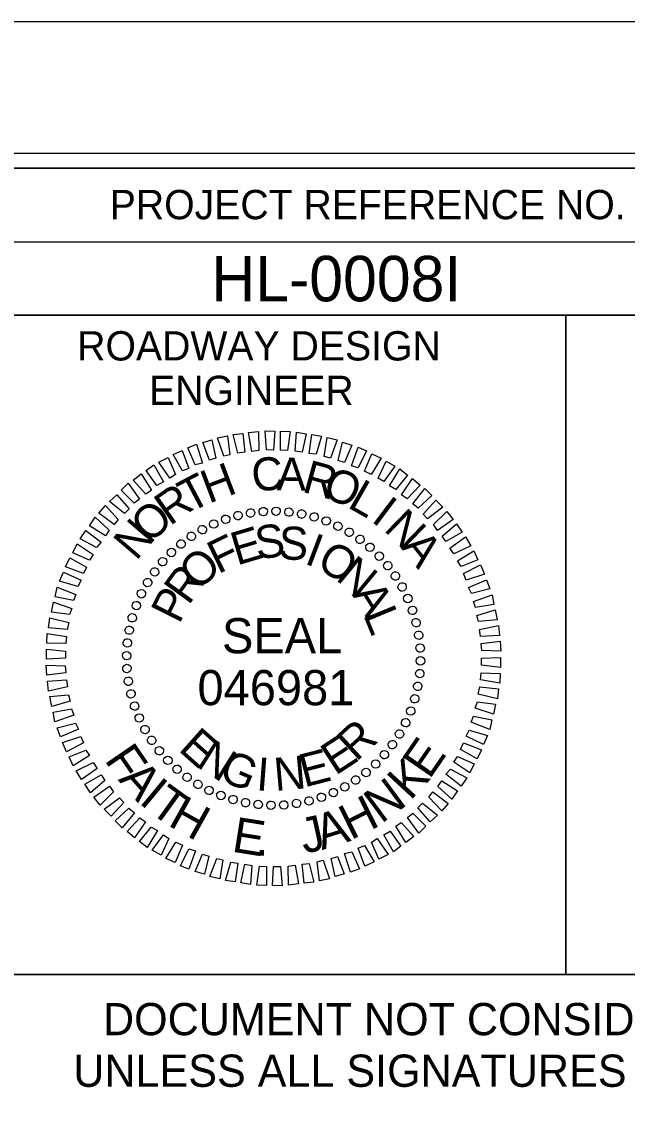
# Model space of a CAD drawing. Extents: x 1629737 to 1631945, y 1172886 to 1173986.
# Drawn here: x 1631211.5 to 1631314.8, y 1173800.4 to 1173985.9 of the extents above; entities that cross this region are included whole.
import ezdxf

# ---------------------------------------------------------------- set-up
doc = ezdxf.new("R2010")
doc.units = 0
for name, color, linetype in [('Sheet Data Field CELL', 7, 'Continuous'), ('Sheet PE Seal Cell', 7, 'Continuous'), ('Sheet Plot Border Inside CELL', 7, 'Continuous'), ('Sheet Plot Border Outside CELL', 7, 'Continuous'), ('Sheet Profile CELL', 7, 'Continuous'), ('Sheet Sticker Exception Certification CELL', 7, 'Continuous')]:
    doc.layers.add(name, color=color, linetype=linetype)

msp = doc.modelspace()

# ---------------------------------------------------------------- linework, layer by layer
at = {"layer": 'Sheet PE Seal Cell'}
for p, q in [((1631250.53, 1173902.1), (1631250.53, 1173902.1)), ((1631252.68, 1173902.4), (1631252.68, 1173902.4)), ((1631254.88, 1173902.45), (1631254.88, 1173902.45)), ((1631257.08, 1173902.3), (1631257.08, 1173902.3)), ((1631244.23, 1173900.3), (1631244.23, 1173900.3)), ((1631246.23, 1173901.1), (1631246.23, 1173901.1)), ((1631248.33, 1173901.7), (1631248.33, 1173901.7)), ((1631259.23, 1173901.95), (1631259.23, 1173901.95)), ((1631261.33, 1173901.5), (1631261.33, 1173901.5)), ((1631263.43, 1173900.8), (1631263.43, 1173900.8)), ((1631242.28, 1173899.3), (1631242.28, 1173899.3)), ((1631265.43, 1173899.9), (1631265.43, 1173899.9)), ((1631267.38, 1173898.9), (1631267.38, 1173898.9)), ((1631238.63, 1173896.9), (1631238.63, 1173896.9)), ((1631240.38, 1173898.15), (1631240.38, 1173898.15)), ((1631269.18, 1173897.65), (1631269.18, 1173897.65)), ((1631236.98, 1173895.4), (1631236.98, 1173895.4)), ((1631270.93, 1173896.3), (1631270.93, 1173896.3)), ((1631272.48, 1173894.8), (1631272.48, 1173894.8)), ((1631235.48, 1173893.85), (1631235.48, 1173893.85)), ((1631273.98, 1173893.15), (1631273.98, 1173893.15)), ((1631234.13, 1173892.1), (1631234.13, 1173892.1)), ((1631275.23, 1173891.4), (1631275.23, 1173891.4)), ((1631232.88, 1173890.3), (1631232.88, 1173890.3)), ((1631276.38, 1173889.5), (1631276.38, 1173889.5)), ((1631231.88, 1173888.35), (1631231.88, 1173888.35)), ((1631277.38, 1173887.55), (1631277.38, 1173887.55)), ((1631230.98, 1173886.35), (1631230.98, 1173886.35)), ((1631278.18, 1173885.55), (1631278.18, 1173885.55)), ((1631230.28, 1173884.25), (1631230.28, 1173884.25)), ((1631229.83, 1173882.15), (1631229.83, 1173882.15)), ((1631278.78, 1173883.45), (1631278.78, 1173883.45)), ((1631229.48, 1173880), (1631229.48, 1173880)), ((1631279.18, 1173881.25), (1631279.18, 1173881.25)), ((1631279.48, 1173879.1), (1631279.48, 1173879.1)), ((1631229.33, 1173877.8), (1631229.33, 1173877.8)), ((1631254.43, 1173877.35), (1631254.43, 1173877.35)), ((1631279.53, 1173876.9), (1631279.53, 1173876.9)), ((1631229.38, 1173875.6), (1631229.38, 1173875.6)), ((1631279.38, 1173874.7), (1631279.38, 1173874.7)), ((1631229.68, 1173873.45), (1631229.68, 1173873.45)), ((1631279.03, 1173872.55), (1631279.03, 1173872.55)), ((1631230.08, 1173871.25), (1631230.08, 1173871.25)), ((1631230.68, 1173869.15), (1631230.68, 1173869.15)), ((1631278.58, 1173870.45), (1631278.58, 1173870.45)), ((1631231.48, 1173867.15), (1631231.48, 1173867.15)), ((1631277.88, 1173868.35), (1631277.88, 1173868.35)), ((1631232.48, 1173865.2), (1631232.48, 1173865.2)), ((1631276.98, 1173866.35), (1631276.98, 1173866.35)), ((1631233.63, 1173863.3), (1631233.63, 1173863.3)), ((1631275.98, 1173864.4), (1631275.98, 1173864.4)), ((1631234.88, 1173861.55), (1631234.88, 1173861.55)), ((1631274.73, 1173862.6), (1631274.73, 1173862.6)), ((1631236.38, 1173859.9), (1631236.38, 1173859.9)), ((1631273.38, 1173860.85), (1631273.38, 1173860.85)), ((1631237.93, 1173858.4), (1631237.93, 1173858.4)), ((1631270.23, 1173857.8), (1631270.23, 1173857.8)), ((1631271.88, 1173859.3), (1631271.88, 1173859.3)), ((1631239.68, 1173857.05), (1631239.68, 1173857.05)), ((1631241.48, 1173855.8), (1631241.48, 1173855.8)), ((1631268.48, 1173856.55), (1631268.48, 1173856.55)), ((1631243.43, 1173854.8), (1631243.43, 1173854.8)), ((1631245.43, 1173853.9), (1631245.43, 1173853.9)), ((1631264.63, 1173854.4), (1631264.63, 1173854.4)), ((1631266.58, 1173855.4), (1631266.58, 1173855.4)), ((1631247.53, 1173853.2), (1631247.53, 1173853.2)), ((1631249.63, 1173852.75), (1631249.63, 1173852.75)), ((1631251.78, 1173852.4), (1631251.78, 1173852.4)), ((1631253.98, 1173852.25), (1631253.98, 1173852.25)), ((1631256.18, 1173852.3), (1631256.18, 1173852.3)), ((1631258.33, 1173852.6), (1631258.33, 1173852.6)), ((1631260.53, 1173853), (1631260.53, 1173853)), ((1631262.63, 1173853.6), (1631262.63, 1173853.6))]:
    msp.add_line(p, q, dxfattribs=at)
for points in [[(1631245.93, 1173911.8), (1631244.88, 1173914.95), (1631246.58, 1173915.3), (1631246.98, 1173912.05)], [(1631248.33, 1173912.35), (1631247.53, 1173915.55), (1631249.18, 1173915.7), (1631249.53, 1173912.5)], [(1631250.73, 1173912.65), (1631250.18, 1173915.85), (1631251.88, 1173916.05), (1631251.93, 1173912.8)], [(1631253.23, 1173912.9), (1631252.98, 1173916.15), (1631254.63, 1173916.1), (1631254.43, 1173912.85)], [(1631255.63, 1173912.85), (1631255.63, 1173916.1), (1631257.28, 1173916.05), (1631256.83, 1173912.8)], [(1631258.13, 1173912.7), (1631258.33, 1173915.95), (1631259.98, 1173915.65), (1631259.33, 1173912.5)], [(1631260.53, 1173912.3), (1631260.98, 1173915.5), (1631262.63, 1173915.25), (1631261.73, 1173912.15)], [(1631241.08, 1173910.35), (1631239.78, 1173913.25), (1631241.28, 1173913.85), (1631242.33, 1173910.65)], [(1631243.53, 1173911.15), (1631242.38, 1173914.15), (1631243.93, 1173914.6), (1631244.58, 1173911.5)], [(1631263.08, 1173911.75), (1631263.58, 1173915), (1631265.28, 1173914.6), (1631264.13, 1173911.5)], [(1631265.48, 1173911.1), (1631266.23, 1173914.2), (1631267.78, 1173913.7), (1631266.53, 1173910.75)], [(1631267.73, 1173910.2), (1631268.88, 1173913.35), (1631270.28, 1173912.75), (1631268.88, 1173909.85)], [(1631236.73, 1173908.1), (1631234.88, 1173910.8), (1631236.43, 1173911.6), (1631237.68, 1173908.7)], [(1631238.88, 1173909.3), (1631237.28, 1173912.1), (1631238.83, 1173912.8), (1631239.98, 1173909.75)], [(1631269.98, 1173909.25), (1631271.23, 1173912.2), (1631272.78, 1173911.5), (1631271.08, 1173908.7)], [(1631234.53, 1173906.85), (1631232.68, 1173909.4), (1631233.98, 1173910.35), (1631235.63, 1173907.45)], [(1631272.28, 1173908.1), (1631273.63, 1173910.95), (1631275.13, 1173910.1), (1631273.23, 1173907.5)], [(1631274.23, 1173906.75), (1631275.98, 1173909.65), (1631277.28, 1173908.6), (1631275.33, 1173906.15)], [(1631232.63, 1173905.35), (1631230.48, 1173907.75), (1631231.83, 1173908.8), (1631233.58, 1173906)], [(1631276.28, 1173905.25), (1631278.13, 1173908), (1631279.43, 1173906.9), (1631277.23, 1173904.55)], [(1631230.63, 1173903.8), (1631228.43, 1173906), (1631229.63, 1173907.2), (1631231.58, 1173904.5)], [(1631278.18, 1173903.7), (1631280.23, 1173906.3), (1631281.43, 1173905.1), (1631279.13, 1173902.95)], [(1631228.98, 1173902.05), (1631226.43, 1173904.1), (1631227.68, 1173905.25), (1631229.78, 1173902.85)], [(1631279.98, 1173901.95), (1631282.13, 1173904.3), (1631283.33, 1173903.1), (1631280.73, 1173901.15)], [(1631227.23, 1173900.15), (1631224.63, 1173902.1), (1631225.73, 1173903.4), (1631227.93, 1173901.05)], [(1631281.73, 1173900.15), (1631284.03, 1173902.4), (1631285.08, 1173901.05), (1631282.43, 1173899.15)], [(1631225.73, 1173898.25), (1631223.03, 1173899.95), (1631223.98, 1173901.4), (1631226.38, 1173899.2)], [(1631283.23, 1173898.2), (1631285.68, 1173900.3), (1631286.63, 1173898.85), (1631283.83, 1173897.25)], [(1631224.23, 1173896.25), (1631221.43, 1173897.75), (1631222.43, 1173899.15), (1631225.03, 1173897.15)], [(1631223.03, 1173894.1), (1631220.18, 1173895.35), (1631220.93, 1173896.9), (1631223.63, 1173895.05)], [(1631284.53, 1173896.15), (1631287.18, 1173898.05), (1631288.13, 1173896.55), (1631285.23, 1173895.15)], [(1631285.83, 1173893.95), (1631288.63, 1173895.7), (1631289.28, 1173894.15), (1631286.43, 1173893)], [(1631222.03, 1173891.8), (1631218.93, 1173892.95), (1631219.68, 1173894.5), (1631222.53, 1173892.9)], [(1631286.83, 1173891.8), (1631289.78, 1173893.3), (1631290.43, 1173891.7), (1631287.33, 1173890.7)], [(1631221.03, 1173889.6), (1631217.93, 1173890.5), (1631218.58, 1173892.05), (1631221.58, 1173890.65)], [(1631220.28, 1173887.2), (1631217.18, 1173887.85), (1631217.53, 1173889.5), (1631220.68, 1173888.25)], [(1631287.73, 1173889.45), (1631290.78, 1173890.75), (1631291.33, 1173889.2), (1631288.23, 1173888.4)], [(1631288.53, 1173887.05), (1631291.73, 1173888.2), (1631292.03, 1173886.55), (1631288.88, 1173886)], [(1631219.63, 1173884.8), (1631216.53, 1173885.2), (1631216.88, 1173886.9), (1631220.03, 1173885.85)], [(1631289.13, 1173884.65), (1631292.28, 1173885.6), (1631292.58, 1173883.9), (1631289.43, 1173883.6)], [(1631219.23, 1173882.25), (1631216.03, 1173882.55), (1631216.23, 1173884.25), (1631219.48, 1173883.45)], [(1631289.58, 1173882.25), (1631292.83, 1173882.95), (1631292.98, 1173881.25), (1631289.78, 1173881.05)], [(1631218.98, 1173879.85), (1631215.73, 1173879.95), (1631215.83, 1173881.6), (1631219.08, 1173881.05)], [(1631289.88, 1173879.85), (1631293.13, 1173880.25), (1631293.23, 1173878.55), (1631289.98, 1173878.65)], [(1631218.93, 1173877.35), (1631215.68, 1173877.2), (1631215.68, 1173878.9), (1631218.93, 1173878.55)], [(1631218.98, 1173874.85), (1631215.73, 1173874.45), (1631215.63, 1173876.15), (1631218.88, 1173876.05)], [(1631289.93, 1173877.35), (1631293.18, 1173877.5), (1631293.18, 1173875.8), (1631289.93, 1173876.15)], [(1631289.88, 1173874.85), (1631293.13, 1173874.75), (1631293.03, 1173873.1), (1631289.78, 1173873.65)], [(1631219.28, 1173872.45), (1631216.03, 1173871.75), (1631215.88, 1173873.45), (1631219.08, 1173873.65)], [(1631289.63, 1173872.45), (1631292.83, 1173872.15), (1631292.63, 1173870.45), (1631289.38, 1173871.25)], [(1631219.73, 1173870.05), (1631216.58, 1173869.1), (1631216.28, 1173870.8), (1631219.43, 1173871.1)], [(1631220.33, 1173867.65), (1631217.13, 1173866.5), (1631216.83, 1173868.15), (1631219.98, 1173868.7)], [(1631289.23, 1173869.9), (1631292.33, 1173869.5), (1631291.98, 1173867.8), (1631288.83, 1173868.85)], [(1631288.58, 1173867.5), (1631291.68, 1173866.85), (1631291.33, 1173865.2), (1631288.18, 1173866.45)], [(1631221.13, 1173865.25), (1631218.08, 1173863.95), (1631217.53, 1173865.5), (1631220.63, 1173866.3)], [(1631287.83, 1173865.1), (1631290.93, 1173864.2), (1631290.28, 1173862.65), (1631287.28, 1173864.05)], [(1631222.03, 1173862.9), (1631219.08, 1173861.4), (1631218.43, 1173863), (1631221.53, 1173864)], [(1631223.03, 1173860.75), (1631220.23, 1173859), (1631219.58, 1173860.55), (1631222.43, 1173861.7)], [(1631286.83, 1173862.9), (1631289.93, 1173861.75), (1631289.18, 1173860.2), (1631286.33, 1173861.8)], [(1631224.33, 1173858.55), (1631221.68, 1173856.65), (1631220.73, 1173858.15), (1631223.63, 1173859.55)], [(1631285.83, 1173860.6), (1631288.68, 1173859.35), (1631287.93, 1173857.8), (1631285.23, 1173859.65)], [(1631284.63, 1173858.45), (1631287.43, 1173856.95), (1631286.43, 1173855.55), (1631283.83, 1173857.55)], [(1631225.63, 1173856.5), (1631223.18, 1173854.4), (1631222.23, 1173855.85), (1631225.03, 1173857.45)], [(1631283.13, 1173856.45), (1631285.83, 1173854.75), (1631284.88, 1173853.3), (1631282.48, 1173855.5)], [(1631227.13, 1173854.55), (1631224.83, 1173852.3), (1631223.78, 1173853.65), (1631226.43, 1173855.55)], [(1631281.63, 1173854.55), (1631284.23, 1173852.6), (1631283.13, 1173851.3), (1631280.93, 1173853.65)], [(1631228.88, 1173852.75), (1631226.73, 1173850.4), (1631225.53, 1173851.6), (1631228.13, 1173853.55)], [(1631279.88, 1173852.65), (1631282.43, 1173850.6), (1631281.18, 1173849.45), (1631279.08, 1173851.85)], [(1631230.68, 1173851), (1631228.63, 1173848.4), (1631227.43, 1173849.6), (1631229.73, 1173851.75)], [(1631232.58, 1173849.45), (1631230.73, 1173846.7), (1631229.43, 1173847.8), (1631231.63, 1173850.15)], [(1631278.23, 1173850.9), (1631280.43, 1173848.7), (1631279.23, 1173847.5), (1631277.28, 1173850.2)], [(1631234.63, 1173847.95), (1631232.88, 1173845.05), (1631231.58, 1173846.1), (1631233.53, 1173848.55)], [(1631276.23, 1173849.35), (1631278.38, 1173846.95), (1631277.03, 1173845.9), (1631275.28, 1173848.7)], [(1631236.58, 1173846.6), (1631235.23, 1173843.75), (1631233.73, 1173844.6), (1631235.63, 1173847.2)], [(1631272.13, 1173846.6), (1631273.98, 1173843.9), (1631272.43, 1173843.1), (1631271.18, 1173846)], [(1631274.33, 1173847.85), (1631276.18, 1173845.3), (1631274.88, 1173844.35), (1631273.23, 1173847.25)], [(1631238.88, 1173845.45), (1631237.63, 1173842.5), (1631236.08, 1173843.2), (1631237.78, 1173846)], [(1631241.13, 1173844.5), (1631239.98, 1173841.35), (1631238.58, 1173841.95), (1631239.98, 1173844.85)], [(1631269.98, 1173845.4), (1631271.58, 1173842.6), (1631270.03, 1173841.9), (1631268.88, 1173844.95)], [(1631243.38, 1173843.6), (1631242.63, 1173840.5), (1631241.08, 1173841), (1631242.33, 1173843.95)], [(1631245.78, 1173842.95), (1631245.28, 1173839.7), (1631243.58, 1173840.1), (1631244.73, 1173843.2)], [(1631262.93, 1173842.9), (1631263.98, 1173839.75), (1631262.28, 1173839.4), (1631261.88, 1173842.65)], [(1631265.33, 1173843.55), (1631266.48, 1173840.55), (1631264.93, 1173840.1), (1631264.28, 1173843.2)], [(1631267.78, 1173844.35), (1631269.08, 1173841.45), (1631267.58, 1173840.85), (1631266.53, 1173844.05)], [(1631248.33, 1173842.4), (1631247.88, 1173839.2), (1631246.23, 1173839.45), (1631247.13, 1173842.55)], [(1631250.73, 1173842), (1631250.53, 1173838.75), (1631248.88, 1173839.05), (1631249.53, 1173842.2)], [(1631253.23, 1173841.85), (1631253.23, 1173838.6), (1631251.58, 1173838.65), (1631252.03, 1173841.9)], [(1631255.63, 1173841.8), (1631255.88, 1173838.55), (1631254.23, 1173838.6), (1631254.43, 1173841.85)], [(1631258.13, 1173842.05), (1631258.68, 1173838.85), (1631256.98, 1173838.65), (1631256.93, 1173841.9)], [(1631260.53, 1173842.35), (1631261.33, 1173839.15), (1631259.68, 1173839), (1631259.33, 1173842.2)]]:
    msp.add_lwpolyline(points, close=True, dxfattribs=at)
for centre, major_axis in [((1631248.37, 1173901.69), (-0.174, 0.699)), ((1631250.51, 1173902.12), (-0.113, 0.711)), ((1631252.68, 1173902.37), (-0.05, 0.718)), ((1631254.87, 1173902.43), (0.013, 0.72)), ((1631257.06, 1173902.29), (0.075, 0.716)), ((1631259.22, 1173901.97), (0.137, 0.707)), ((1631261.35, 1173901.46), (0.198, 0.692)), ((1631244.23, 1173900.26), (-0.293, 0.658)), ((1631246.27, 1173901.07), (-0.234, 0.681)), ((1631263.42, 1173900.77), (0.258, 0.672)), ((1631265.43, 1173899.89), (0.316, 0.647)), ((1631240.41, 1173898.14), (-0.403, 0.597)), ((1631242.28, 1173899.29), (-0.349, 0.63)), ((1631267.35, 1173898.85), (0.371, 0.617)), ((1631269.18, 1173897.64), (0.423, 0.582)), ((1631238.65, 1173896.84), (-0.453, 0.56)), ((1631270.89, 1173896.28), (0.472, 0.543)), ((1631235.51, 1173893.81), (-0.543, 0.472)), ((1631237.01, 1173895.39), (-0.5, 0.518)), ((1631272.48, 1173894.77), (0.518, 0.5)), ((1631234.14, 1173892.09), (-0.582, 0.423)), ((1631273.93, 1173893.14), (0.56, 0.453)), ((1631232.94, 1173890.27), (-0.617, 0.371)), ((1631275.23, 1173891.38), (0.597, 0.403)), ((1631231.89, 1173888.35), (-0.647, 0.316)), ((1631276.37, 1173889.51), (0.63, 0.349)), ((1631277.35, 1173887.55), (0.658, 0.293)), ((1631231.02, 1173886.34), (-0.672, 0.258)), ((1631278.15, 1173885.52), (0.681, 0.234)), ((1631230.33, 1173884.26), (-0.692, 0.198)), ((1631278.77, 1173883.42), (0.699, 0.174)), ((1631229.82, 1173882.14), (-0.707, 0.137)), ((1631279.21, 1173881.28), (0.711, 0.113)), ((1631229.49, 1173879.97), (-0.716, 0.075)), ((1631279.45, 1173879.1), (0.718, 0.05)), ((1631229.36, 1173877.79), (-0.72, 0.013)), ((1631229.42, 1173875.6), (-0.718, -0.05)), ((1631279.51, 1173876.91), (0.72, -0.013)), ((1631229.66, 1173873.43), (-0.711, -0.113)), ((1631279.38, 1173874.73), (0.716, -0.075)), ((1631279.05, 1173872.57), (0.707, -0.137)), ((1631230.1, 1173871.28), (-0.699, -0.174)), ((1631278.54, 1173870.44), (0.692, -0.198)), ((1631230.72, 1173869.19), (-0.681, -0.234)), ((1631277.85, 1173868.36), (0.672, -0.258)), ((1631231.52, 1173867.15), (-0.658, -0.293)), ((1631276.98, 1173866.36), (0.647, -0.316)), ((1631232.5, 1173865.19), (-0.63, -0.349)), ((1631275.93, 1173864.43), (0.617, -0.371)), ((1631233.64, 1173863.33), (-0.597, -0.403)), ((1631274.72, 1173862.61), (0.582, -0.423)), ((1631234.94, 1173861.57), (-0.56, -0.453)), ((1631273.36, 1173860.9), (0.543, -0.472)), ((1631236.39, 1173859.93), (-0.518, -0.5)), ((1631271.86, 1173859.31), (0.5, -0.518)), ((1631237.98, 1173858.42), (-0.472, -0.543)), ((1631239.69, 1173857.06), (-0.423, -0.582)), ((1631270.22, 1173857.86), (0.453, -0.56)), ((1631241.52, 1173855.85), (-0.371, -0.617)), ((1631266.59, 1173855.42), (0.349, -0.63)), ((1631268.46, 1173856.56), (0.403, -0.597)), ((1631243.44, 1173854.81), (-0.316, -0.647)), ((1631245.45, 1173853.94), (-0.258, -0.672)), ((1631247.52, 1173853.24), (-0.198, -0.692)), ((1631260.5, 1173853.02), (0.174, -0.699)), ((1631262.6, 1173853.64), (0.234, -0.681)), ((1631264.64, 1173854.44), (0.293, -0.658)), ((1631249.65, 1173852.73), (-0.137, -0.707)), ((1631251.81, 1173852.41), (-0.075, -0.716)), ((1631254, 1173852.28), (-0.013, -0.72)), ((1631256.18, 1173852.33), (0.05, -0.718)), ((1631258.36, 1173852.58), (0.113, -0.711))]:
    msp.add_ellipse(centre, major_axis=major_axis, ratio=0.999708, dxfattribs=at)
at = {"layer": 'Sheet Plot Border Inside CELL'}
msp.add_lwpolyline([(1629750.31, 1172908.39), (1631416.81, 1172908.39), (1631416.81, 1173963.49), (1629750.31, 1173963.49)], close=True, dxfattribs=at)
at = {"layer": 'Sheet Plot Border Outside CELL'}
msp.add_lwpolyline([(1629737.31, 1172885.94), (1631421.31, 1172885.94), (1631421.31, 1173985.94), (1629737.31, 1173985.94)], close=True, dxfattribs=at)
at = {"layer": 'Sheet Profile CELL'}
for p, q in [((1631204.26, 1173948.39), (1631404.31, 1173948.39)), ((1631304.31, 1173935.89), (1631304.31, 1173823.44))]:
    msp.add_line(p, q, dxfattribs=at)
for points in [[(1631404.31, 1173960.94), (1629904.31, 1173960.94), (1629904.31, 1172910.94), (1631404.31, 1172910.94)], [(1631204.26, 1173960.94), (1631404.31, 1173960.94), (1631404.31, 1173935.89), (1631204.26, 1173935.89)], [(1631204.26, 1173935.89), (1631304.31, 1173935.89), (1631304.31, 1173823.39), (1631204.26, 1173823.39)], [(1631304.31, 1173935.89), (1631404.31, 1173935.89), (1631404.31, 1173823.39), (1631304.31, 1173823.39)]]:
    msp.add_lwpolyline(points, close=True, dxfattribs=at)
at = {"layer": 'Sheet Sticker Exception Certification CELL'}
msp.add_line((1631204.26, 1173823.39), (1631404.3, 1173823.39), dxfattribs=at)

# ---------------------------------------------------------------- texts
at = {"layer": 'Sheet Data Field CELL'}
msp.add_text('HL-0008I', height=7.75, rotation=360, dxfattribs=at).set_placement((1631243.83, 1173938.25))
at = {"layer": 'Sheet PE Seal Cell'}
for s, height, rotation, p in [('C', 5.64, 6.2199, (1631250.98, 1173905.7)), ('A', 5.64, 359.0203, (1631254.93, 1173906)), ('H', 5.64, 20.6195, (1631243.38, 1173903.7)), ('R', 5.64, 344.6211, (1631259.13, 1173905.8)), ('O', 5.64, 337.4212, (1631262.48, 1173905.05)), ('T', 5.64, 27.8198, (1631240.13, 1173902.05)), ('L', 5.64, 330.2209, (1631266.88, 1173903.2)), ('R', 5.64, 35.0205, (1631236.73, 1173899.85)), ('I', 5.64, 323.0201, (1631270.93, 1173900.8)), ('O', 5.64, 42.2217, (1631233.28, 1173896.75)), ('N', 5.64, 315.8189, (1631273.08, 1173899.25)), ('N', 5.64, 49.4235, (1631230.98, 1173893.85)), ('S', 5.64, 7.2556, (1631251.63, 1173894.2)), ('F', 5.64, 25.967, (1631244.98, 1173891.65)), ('E', 5.64, 16.6111, (1631248.18, 1173893.15)), ('S', 5.64, 357.9004, (1631255.23, 1173894.25)), ('I', 5.64, 339.1896, (1631259.53, 1173893.55)), ('O', 5.64, 329.8335, (1631261.53, 1173892.85)), ('A', 5.64, 308.6172, (1631276.03, 1173896.3)), ('O', 5.64, 44.6812, (1631241.68, 1173888.7)), ('N', 5.64, 320.4766, (1631264.88, 1173890.85)), ('R', 5.64, 54.0397, (1631239.93, 1173886.25)), ('P', 5.64, 63.3989, (1631238.33, 1173883.05)), ('A', 5.64, 301.7603, (1631267.73, 1173888.25)), ('L', 5.64, 292.4009, (1631269.68, 1173884.8)), ('SEAL', 5.998, 360, (1631245.64, 1173878.2)), ('E', 5.64, 318.2769, (1631238.03, 1173861.7)), ('R', 5.64, 42.4814, (1631268.53, 1173859.6)), ('N', 5.64, 327.634, (1631241.03, 1173859)), ('E', 5.64, 33.1241, (1631264.98, 1173857.25)), ('E', 6, 55.493, (1631281.04, 1173856.56)), ('F', 6, 304.4142, (1631225.47, 1173860.01)), ('G', 5.64, 336.9902, (1631244.83, 1173856.75)), ('E', 5.64, 14.4118, (1631259.68, 1173855.3)), ('I', 5.64, 355.7012, (1631251.38, 1173854.85)), ('N', 5.64, 5.0564, (1631254.73, 1173854.7)), ('K', 6, 47.2091, (1631277.76, 1173852.94)), ('A', 6, 311.4309, (1631227.8, 1173856.6)), ('I', 6, 320.2712, (1631231.31, 1173852.75)), ('T', 6, 324.0731, (1631232.99, 1173851.27)), ('N', 6, 36.4833, (1631272.81, 1173849.03)), ('H', 6, 330.8733, (1631236.23, 1173848.92)), ('H', 6, 26.4993, (1631267.62, 1173846.27)), ('E', 6, 351.0577, (1631247.16, 1173844.38)), ('J', 6, 12.4012, (1631259.66, 1173843.99)), ('A', 6, 17.659, (1631262.69, 1173844.61)), ('.', 6, 358.167, (1631251.29, 1173843.73))]:
    msp.add_text(s, height=height, rotation=rotation, dxfattribs=at).set_placement(p)
msp.add_text('046981', height=5.998, dxfattribs=at).set_placement((1631241.46, 1173869.34))
at = {"layer": 'Sheet Profile CELL'}
for s, height, p in [('PROJECT REFERENCE NO.', 5.0001, (1631226.48, 1173952.25)), ('ROADWAY DESIGN', 5.0001, (1631220.93, 1173928.15)), ('ENGINEER', 5, (1631233.18, 1173920.55))]:
    msp.add_text(s, height=height, rotation=360, dxfattribs=at).set_placement(p)
at = {"layer": 'Sheet Sticker Exception Certification CELL'}
for s, p in [('DOCUMENT NOT CONSIDERED FINAL', (1631225.33, 1173813.04)), ('UNLESS ALL SIGNATURES COMPLETED', (1631220.26, 1173804.24))]:
    msp.add_text(s, height=5.5, rotation=360, dxfattribs=at).set_placement(p)

doc.saveas('drawing.dxf')
